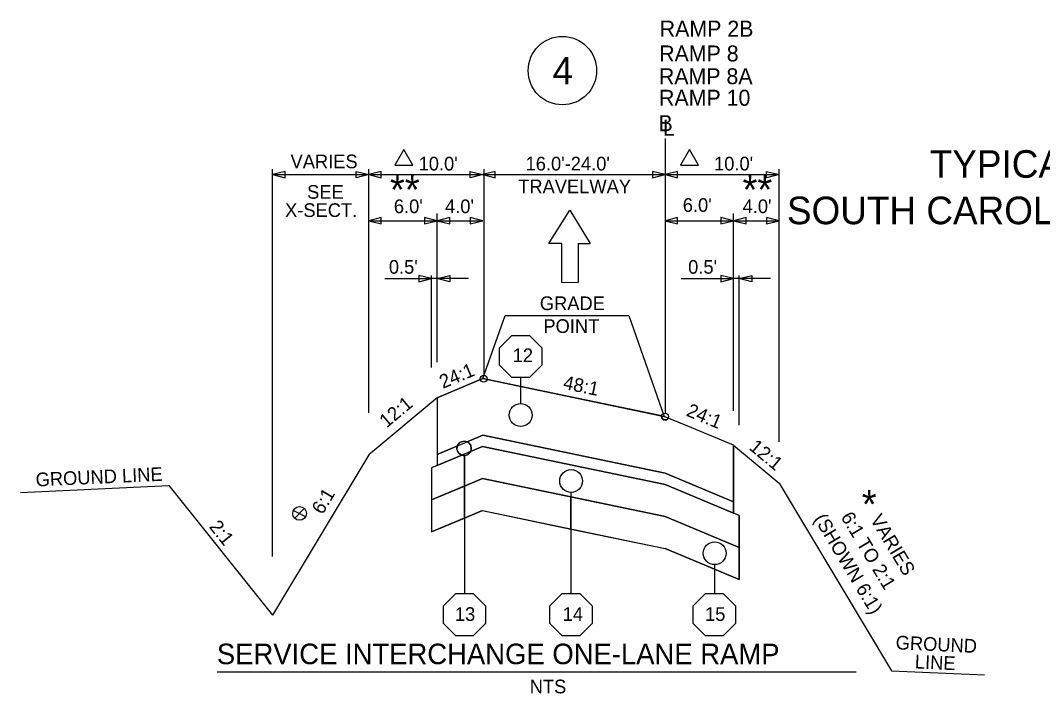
# Model space of a CAD drawing. Extents: x 4932 to 5887, y 4809 to 5473.
# Drawn here: x 5031.4 to 5121, y 5160 to 5219 of the extents above; entities that cross this region are included whole.
import ezdxf

# ---------------------------------------------------------------- set-up
doc = ezdxf.new("R2010")
doc.units = 0
for name, color, linetype in [('Level 20', 7, 'Continuous'), ('Level 25', 7, 'Continuous'), ('RD_QTY_Miscl_1', 7, 'Continuous'), ('RD_QTY_Miscl_2', 7, 'Continuous'), ('RD_QTY_Miscl_3', 7, 'Continuous'), ('RD_QTY_Miscl_4', 7, 'Continuous'), ('RD_SHT_TX', 7, 'Continuous'), ('RD_SHT_Typical', 7, 'Continuous'), ('RD_TX_TypSect', 7, 'Continuous'), ('RD_XS_ExGround', 7, 'Continuous'), ('typical_on', 7, 'Continuous')]:
    doc.layers.add(name, color=color, linetype=linetype)

msp = doc.modelspace()

# ---------------------------------------------------------------- linework, layer by layer
at = {"layer": 'Level 20'}
for p, q in [((5077.716, 5199.412), (5079.538, 5202.327)), ((5079.538, 5202.327), (5081.322, 5199.403)), ((5078.809, 5199.412), (5077.716, 5199.412)), ((5078.809, 5199.412), (5078.809, 5196.011)), ((5080.265, 5199.403), (5081.322, 5199.403)), ((5080.265, 5199.403), (5080.265, 5196.003)), ((5078.809, 5196.011), (5080.265, 5196.003))]:
    msp.add_line(p, q, dxfattribs=at)
at = {"layer": 'Level 25'}
for p, q in [((5071.923, 5187.571), (5073.866, 5193.106)), ((5073.866, 5193.106), (5084.722, 5193.106)), ((5084.722, 5193.106), (5087.828, 5184.257))]:
    msp.add_line(p, q, dxfattribs=at)
msp.add_circle((5078.891, 5214.568), 3, dxfattribs=at)
at = {"layer": 'RD_QTY_Miscl_1'}
for p, q in [((5071.923, 5187.571), (5069.844, 5186.704)), ((5069.844, 5186.704), (5067.903, 5185.895)), ((5067.903, 5185.895), (5067.903, 5180.931)), ((5089.895, 5183.396), (5088.166, 5184.117)), ((5070.533, 5182.027), (5071.923, 5182.606)), ((5071.923, 5182.606), (5087.895, 5179.279)), ((5093.893, 5181.73), (5089.895, 5183.396)), ((5067.903, 5180.931), (5069.682, 5181.672)), ((5093.893, 5176.78), (5093.893, 5181.73)), ((5087.895, 5179.279), (5093.893, 5176.78))]:
    msp.add_line(p, q, dxfattribs=at)
msp.add_lwpolyline([(5087.6, 5184.305), (5075.233, 5186.881), (5071.923, 5187.571)], dxfattribs=at)
msp.add_circle((5075.233, 5184.377), 1, dxfattribs=at)
for centre, radius, start, end in [((5087.894, 5184.244), 0.3, 168.23191, 334.96624), ((5070.273, 5181.453), 0.63, 65.59282, 159.64528)]:
    msp.add_arc(centre, radius, start, end, dxfattribs=at)
at = {"layer": 'RD_QTY_Miscl_2'}
for p, q in [((5071.923, 5182.606), (5070.533, 5182.027)), ((5087.895, 5179.279), (5071.923, 5182.606)), ((5069.682, 5181.672), (5067.903, 5180.931)), ((5070.84, 5181.18), (5071.896, 5181.62)), ((5071.896, 5181.62), (5087.894, 5178.287)), ((5067.903, 5180.931), (5067.903, 5179.957)), ((5067.903, 5179.957), (5070.067, 5180.858)), ((5093.893, 5176.78), (5087.895, 5179.279)), ((5087.894, 5178.287), (5093.893, 5175.788)), ((5093.893, 5175.788), (5093.893, 5176.78))]:
    msp.add_line(p, q, dxfattribs=at)
for start, end in [(159.64528, 250.93779), (334.30193, 65.59282)]:
    msp.add_arc((5070.273, 5181.453), 0.63, start, end, dxfattribs=at)
at = {"layer": 'RD_QTY_Miscl_3'}
for p, q in [((5071.896, 5181.62), (5070.84, 5181.18)), ((5087.894, 5178.287), (5071.896, 5181.62)), ((5070.296, 5180.824), (5070.296, 5178.143)), ((5070.296, 5178.143), (5070.296, 5180.824)), ((5067.403, 5179.748), (5067.403, 5176.937)), ((5067.403, 5176.937), (5070.296, 5178.143)), ((5070.296, 5178.143), (5071.896, 5178.809)), ((5093.893, 5175.788), (5087.894, 5178.287)), ((5087.894, 5175.476), (5094.391, 5172.769)), ((5094.393, 5175.579), (5093.893, 5175.788)), ((5094.393, 5172.769), (5094.393, 5175.579))]:
    msp.add_line(p, q, dxfattribs=at)
for points in [[(5070.067, 5180.858), (5067.903, 5179.957), (5067.403, 5179.748)], [(5071.896, 5178.809), (5079.644, 5177.195), (5087.894, 5175.476)], [(5094.391, 5172.769), (5094.393, 5172.769)]]:
    msp.add_lwpolyline(points, dxfattribs=at)
msp.add_circle((5079.659, 5178.596), 1, dxfattribs=at)
for start, end in [(250.93779, 272.14599), (272.14599, 334.30193)]:
    msp.add_arc((5070.273, 5181.453), 0.63, start, end, dxfattribs=at)
at = {"layer": 'RD_QTY_Miscl_4'}
for p, q in [((5070.296, 5178.143), (5067.403, 5176.937)), ((5071.896, 5178.809), (5070.296, 5178.143)), ((5070.296, 5178.143), (5070.296, 5175.331)), ((5070.296, 5175.331), (5070.296, 5178.143)), ((5079.644, 5177.195), (5071.896, 5178.809)), ((5079.644, 5174.384), (5079.644, 5177.195)), ((5087.894, 5175.476), (5079.644, 5177.195)), ((5079.644, 5177.195), (5079.644, 5174.384)), ((5070.296, 5175.331), (5071.896, 5175.998)), ((5071.896, 5175.998), (5079.644, 5174.384)), ((5094.391, 5172.769), (5087.894, 5175.476)), ((5067.403, 5174.126), (5070.296, 5175.331)), ((5079.644, 5174.384), (5087.894, 5172.665)), ((5094.393, 5169.957), (5094.393, 5172.769))]:
    msp.add_line(p, q, dxfattribs=at)
for points in [[(5067.403, 5176.937), (5067.403, 5176.935), (5067.403, 5174.126)], [(5087.894, 5172.665), (5092.218, 5170.863), (5094.393, 5169.957)], [(5094.393, 5172.769), (5094.391, 5172.769)]]:
    msp.add_lwpolyline(points, dxfattribs=at)
msp.add_circle((5092.248, 5172.262), 1, dxfattribs=at)
at = {"layer": 'RD_SHT_Typical'}
for p, q in [((5069.844, 5186.704), (5071.923, 5187.571)), ((5067.903, 5185.895), (5069.844, 5186.704)), ((5067.903, 5185.895), (5061.905, 5180.897)), ((5067.903, 5185.895), (5067.903, 5179.957)), ((5089.895, 5183.396), (5087.828, 5184.257)), ((5067.903, 5180.931), (5071.923, 5182.606)), ((5093.893, 5181.73), (5089.895, 5183.396)), ((5071.896, 5181.62), (5067.397, 5179.746)), ((5093.893, 5181.73), (5093.893, 5175.788)), ((5093.893, 5181.73), (5097.891, 5178.398)), ((5061.905, 5180.897), (5053.469, 5166.838)), ((5067.403, 5179.748), (5067.403, 5174.126)), ((5093.893, 5176.78), (5087.895, 5179.279)), ((5044.384, 5178.195), (5053.469, 5166.838)), ((5071.896, 5178.809), (5067.397, 5176.935)), ((5094.391, 5175.58), (5087.894, 5178.287)), ((5097.891, 5178.398), (5107.752, 5161.964)), ((5071.896, 5175.998), (5067.403, 5174.126)), ((5094.391, 5172.769), (5087.894, 5175.476)), ((5094.393, 5175.579), (5094.393, 5169.957)), ((5094.393, 5169.957), (5087.894, 5172.665))]:
    msp.add_line(p, q, dxfattribs=at)
for points in [[(5071.923, 5187.571), (5087.828, 5184.257)], [(5071.923, 5182.606), (5087.895, 5179.279)], [(5071.896, 5181.62), (5087.894, 5178.287)], [(5071.896, 5178.809), (5087.894, 5175.476)], [(5071.896, 5175.998), (5087.894, 5172.665)]]:
    msp.add_lwpolyline(points, dxfattribs=at)
at = {"layer": 'RD_TX_TypSect'}
for p, q in [((5087.894, 5208.622), (5087.894, 5184.606)), ((5053.469, 5171.986), (5053.469, 5205.936)), ((5061.905, 5184.568), (5061.905, 5205.936)), ((5071.989, 5205.936), (5071.989, 5187.919)), ((5097.891, 5182.04), (5097.891, 5205.936)), ((5053.469, 5205.451), (5061.905, 5205.451)), ((5061.905, 5205.451), (5071.901, 5205.451)), ((5071.901, 5205.451), (5087.895, 5205.451)), ((5087.895, 5205.451), (5097.891, 5205.451)), ((5061.905, 5201.413), (5067.903, 5201.413)), ((5067.903, 5189.023), (5067.903, 5202.032)), ((5067.903, 5201.413), (5071.901, 5201.413)), ((5087.895, 5201.413), (5093.893, 5201.413)), ((5093.893, 5184.749), (5093.893, 5202.032)), ((5093.893, 5201.413), (5097.891, 5201.413)), ((5063.325, 5196.336), (5067.403, 5196.336)), ((5067.403, 5188.541), (5067.403, 5196.611)), ((5070.668, 5196.336), (5067.403, 5196.336)), ((5089.306, 5196.336), (5093.893, 5196.336)), ((5097.158, 5196.336), (5093.893, 5196.336)), ((5094.393, 5183.484), (5094.393, 5196.611)), ((5075.233, 5185.376), (5075.233, 5187.658)), ((5070.296, 5180.824), (5070.296, 5168.724)), ((5079.644, 5177.596), (5079.644, 5168.724)), ((5055.298, 5176.022), (5056.37, 5175.474)), ((5055.421, 5175.329), (5056.247, 5176.173)), ((5092.218, 5171.263), (5092.218, 5168.724)), ((5048.607, 5161.87), (5104.662, 5161.87))]:
    msp.add_line(p, q, dxfattribs=at)
for points in [[(5064.985, 5207.651), (5064.186, 5206.267), (5065.784, 5206.267)], [(5090.041, 5207.651), (5089.242, 5206.267), (5090.841, 5206.267)], [(5054.572, 5205.176), (5054.572, 5205.726), (5053.469, 5205.451)], [(5060.802, 5205.176), (5060.802, 5205.726), (5061.905, 5205.451)], [(5063.008, 5205.176), (5063.008, 5205.726), (5061.905, 5205.451)], [(5070.798, 5205.176), (5070.798, 5205.726), (5071.901, 5205.451)], [(5073.004, 5205.176), (5073.004, 5205.726), (5071.901, 5205.451)], [(5086.793, 5205.726), (5086.793, 5205.176), (5087.895, 5205.451)], [(5088.998, 5205.176), (5088.998, 5205.726), (5087.895, 5205.451)], [(5096.789, 5205.176), (5096.789, 5205.726), (5097.891, 5205.451)], [(5063.008, 5201.138), (5063.008, 5201.688), (5061.905, 5201.413)], [(5066.8, 5201.688), (5066.8, 5201.138), (5067.903, 5201.413)], [(5069.005, 5201.138), (5069.005, 5201.688), (5067.903, 5201.413)], [(5070.798, 5201.688), (5070.798, 5201.138), (5071.901, 5201.413)], [(5088.998, 5201.138), (5088.998, 5201.688), (5087.895, 5201.413)], [(5092.79, 5201.688), (5092.79, 5201.138), (5093.893, 5201.413)], [(5094.996, 5201.138), (5094.996, 5201.688), (5093.893, 5201.413)], [(5096.789, 5201.688), (5096.789, 5201.138), (5097.891, 5201.413)], [(5066.3, 5196.611), (5066.3, 5196.061), (5067.403, 5196.336)], [(5069.005, 5196.611), (5069.005, 5196.061), (5067.903, 5196.336)], [(5092.79, 5196.611), (5092.79, 5196.061), (5093.893, 5196.336)], [(5095.495, 5196.611), (5095.495, 5196.061), (5094.393, 5196.336)]]:
    msp.add_lwpolyline(points, close=True, dxfattribs=at)
for centre, radius in [((5071.989, 5187.557), 0.3), ((5075.233, 5184.377), 1), ((5087.894, 5184.244), 0.3), ((5087.894, 5184.244), 0.3), ((5070.273, 5181.453), 0.63), ((5079.659, 5178.596), 1), ((5055.839, 5175.754), 0.6), ((5092.248, 5172.262), 1)]:
    msp.add_circle(centre, radius, dxfattribs=at)
at = {"layer": 'RD_XS_ExGround'}
for p, q in [((5031.358, 5177.601), (5044.384, 5178.195)), ((5107.752, 5161.964), (5115.899, 5161.592))]:
    msp.add_line(p, q, dxfattribs=at)
at = {"layer": 'typical_on'}
for points in [[(5077.08, 5190.27), (5077.08, 5188.74), (5075.998, 5187.658), (5074.468, 5187.658), (5073.387, 5188.74), (5073.387, 5190.27), (5074.468, 5191.351), (5075.998, 5191.351)], [(5072.143, 5167.642), (5072.143, 5166.113), (5071.061, 5165.031), (5069.532, 5165.031), (5068.45, 5166.113), (5068.45, 5167.642), (5069.531, 5168.724), (5071.061, 5168.724)], [(5081.491, 5167.642), (5081.491, 5166.113), (5080.409, 5165.031), (5078.88, 5165.031), (5077.798, 5166.113), (5077.798, 5167.642), (5078.88, 5168.724), (5080.409, 5168.724)], [(5094.064, 5167.642), (5094.065, 5166.113), (5092.983, 5165.031), (5091.453, 5165.031), (5090.372, 5166.113), (5090.372, 5167.642), (5091.453, 5168.724), (5092.983, 5168.724)]]:
    msp.add_lwpolyline(points, close=True, dxfattribs=at)

# ---------------------------------------------------------------- texts
at = {"layer": 'Level 25'}
msp.add_text('4', height=2.4, dxfattribs=at).set_placement((5078.031, 5213.368))
at = {"layer": 'RD_SHT_TX'}
for s, p in [('TYPICAL SECTION OF IMPROVEMENT', (5111.111, 5205.173)), ('SOUTH CAROLINA DEPARTMENT OF TRANSPORTATION', (5098.585, 5201.104))]:
    msp.add_text(s, height=2.42031, dxfattribs=at).set_placement(p)
at = {"layer": 'RD_TX_TypSect'}
for s, height, p in [('RAMP 2B', 1.4, (5087.428, 5217.544)), ('RAMP 8', 1.4, (5087.377, 5215.371)), ('RAMP 8A', 1.4, (5087.354, 5213.376)), ('RAMP 10', 1.4, (5087.367, 5211.487)), ('B', 1.4, (5087.322, 5209.257)), ('L', 1.4, (5087.694, 5208.87)), ('VARIES', 1.2, (5055.048, 5206.006)), ("10.0'", 1.2, (5066.281, 5205.814)), ("16.0'-24.0'", 1.2, (5075.663, 5205.814)), ("10.0'", 1.2, (5092.191, 5205.814)), ('**', 2.5, (5063.769, 5202.889)), ('TRAVELWAY', 1.2, (5075.013, 5203.815)), ('**', 2.5, (5094.694, 5202.889)), ('SEE', 1.2, (5056.504, 5203.335)), ("6.0'", 1.2, (5064.109, 5202.075)), ("4.0'", 1.2, (5068.597, 5202.075)), ("6.0'", 1.2, (5089.451, 5202.186)), ("4.0'", 1.2, (5094.697, 5202.075)), ('X-SECT.', 1.2, (5054.568, 5201.738)), ("0.5'", 1.2, (5063.671, 5196.763)), ("0.5'", 1.2, (5089.921, 5196.763)), ('GRADE', 1.2, (5076.912, 5193.574)), ('POINT', 1.2, (5077.223, 5191.574)), ('12', 1.2, (5074.529, 5189.013)), ('*', 2.5, (5105.15, 5175.314)), ('13', 1.2, (5069.463, 5166.333)), ('14', 1.2, (5078.915, 5166.333)), ('15', 1.2, (5091.402, 5166.333)), ('SERVICE INTERCHANGE ONE-LANE RAMP', 1.8, (5048.586, 5162.538)), ('NTS', 1.2, (5076.021, 5159.982))]:
    msp.add_text(s, height=height, dxfattribs=at).set_placement(p)
for s, rotation, p in [('24:1', 22.61905, (5068.408, 5186.669)), ('48:1', 348.23171, (5078.892, 5186.684)), ('12:1', 39.80557, (5063.467, 5183.195)), ('24:1', 337.38014, (5089.681, 5184.339)), ('12:1', 320.19386, (5095.186, 5181.428)), ('GROUND LINE', 2.60954, (5032.719, 5178.109)), ('6:1', 59.03624, (5057.857, 5175.586)), ('(SHOWN 6:1)', 300.96376, (5100.918, 5175.286)), ('6:1 TO 2:1', 300.96376, (5103.273, 5175.443)), ('VARIES', 300.96376, (5105.848, 5175.231)), ('2:1', 308.65981, (5047.849, 5174.569)), ('GROUND', 357.39046, (5108.101, 5163.848)), ('LINE', 357.39046, (5109.784, 5162.173))]:
    msp.add_text(s, height=1.2, rotation=rotation, dxfattribs=at).set_placement(p)

doc.saveas('drawing.dxf')
